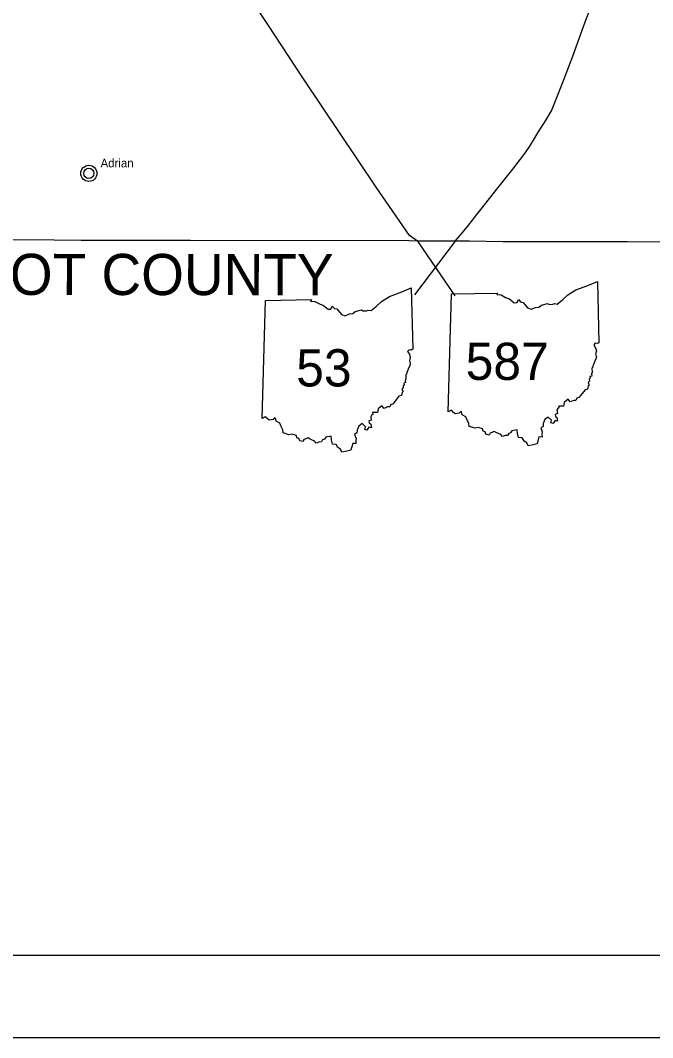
# Model space of a CAD drawing. Extents: x 0 to 882, y 0 to 440.
# Drawn here: x 198.3 to 275.2, y 0 to 123.7 of the extents above; entities that cross this region are included whole.
import ezdxf

# ---------------------------------------------------------------- set-up
doc = ezdxf.new("R2010")
doc.units = 0
for name, color, linetype in [('DV_X_Corp_Line', 7, 'Continuous'), ('GM_X_Adjacent_County_Text', 7, 'Continuous'), ('GM_X_County', 7, 'Continuous'), ('GM_X_State_Route', 7, 'Continuous'), ('PV_P_Text', 7, 'Continuous'), ('SH_Border', 7, 'Continuous'), ('SH_Cut_Line', 7, 'Continuous')]:
    doc.layers.add(name, color=color, linetype=linetype)

msp = doc.modelspace()

# ---------------------------------------------------------------- linework, layer by layer
at = {"layer": 'DV_X_Corp_Line'}
for radius in [0.982, 0.623]:
    msp.add_circle((206.66, 105.09), radius, dxfattribs=at)
at = {"layer": 'GM_X_County'}
msp.add_lwpolyline([(288.04, 96.73), (272.14, 96.76), (257.02, 96.78), (252.97, 96.84), (251.84, 96.84), (251.2, 96.83), (250.6, 96.83), (248.98, 96.85), (246.64, 96.86), (245.6, 96.87), (219.03, 96.94), (205.74, 96.92), (202.42, 96.96), (179.18, 97.04)], dxfattribs=at)
at = {"layer": 'GM_X_State_Route'}
for p, q in [((251.2, 96.83), (246.28, 90.34)), ((246.64, 96.86), (251.16, 90.19))]:
    msp.add_line(p, q, dxfattribs=at)
for points in [[(246.64, 96.86), (245.65, 97.52), (241.61, 103.4), (237.16, 110.07), (232.76, 116.59), (228.43, 123.2), (225.14, 128.19), (224.68, 128.87), (224.33, 129.39), (223.95, 129.96), (219.55, 136.71), (219.48, 136.82), (215.2, 143.29), (212.66, 147.14)], [(254.33, 100.7), (256.44, 103.39), (258.23, 105.6), (259.68, 107.49), (260.38, 108.5), (260.76, 109.14), (261.29, 110), (262.29, 111.6), (262.93, 112.69), (263.52, 114.12), (264.28, 116.06), (265.51, 119.32), (266.87, 123.06), (269.35, 129.63)], [(251.2, 96.83), (252.2, 97.98), (252.87, 98.83), (253.31, 99.4), (253.57, 99.73), (253.84, 100.08), (254.33, 100.7)]]:
    msp.add_lwpolyline(points, dxfattribs=at)
at = {"layer": 'PV_P_Text'}
for p, q in [((250.38, 76.08), (250.78, 90.44)), ((250.38, 76.08), (250.78, 90.44)), ((227.74, 75.28), (228.14, 89.65)), ((227.74, 75.28), (228.14, 89.65))]:
    msp.add_line(p, q, dxfattribs=at)
for points in [[(250.78, 90.44), (256.36, 90.53), (256.27, 90.36), (256.8, 90.32), (257.35, 90.01), (257.83, 89.82), (258.4, 89.36), (258.75, 89.37), (258.9, 89.74), (259.16, 89.45), (259.48, 89.4), (260.02, 88.72), (260.47, 88.57), (261, 88.8), (261.41, 88.84), (261.7, 89.07), (262.46, 89.27), (262.68, 89.15), (263.08, 89.18), (263.29, 89.27), (263.64, 89.19), (264.26, 89.71), (264.9, 90.33), (265.88, 90.91), (267.35, 91.46), (268.52, 91.95), (268.69, 84.5)], [(250.78, 90.44), (256.36, 90.53), (256.27, 90.36), (256.8, 90.32), (257.35, 90.01), (257.83, 89.82), (258.4, 89.36), (258.75, 89.37), (258.9, 89.74), (259.16, 89.45), (259.48, 89.4), (260.02, 88.72), (260.47, 88.57), (261, 88.8), (261.41, 88.84), (261.7, 89.07), (262.46, 89.27), (262.68, 89.15), (263.08, 89.18), (263.29, 89.27), (263.64, 89.19), (264.26, 89.71), (264.9, 90.33), (265.88, 90.91), (267.35, 91.46), (268.52, 91.95), (268.69, 84.5)], [(228.14, 89.65), (233.72, 89.74), (233.63, 89.57), (234.16, 89.53), (234.71, 89.22), (235.19, 89.03), (235.76, 88.57), (236.11, 88.58), (236.26, 88.95), (236.52, 88.66), (236.84, 88.61), (237.38, 87.92), (237.83, 87.78), (238.36, 88.01), (238.77, 88.05), (239.06, 88.28), (239.82, 88.48), (240.04, 88.36), (240.44, 88.39), (240.65, 88.47), (241, 88.4), (241.62, 88.92), (242.26, 89.53), (243.24, 90.11), (244.71, 90.67), (245.88, 91.16), (246.05, 83.7)], [(228.14, 89.65), (233.72, 89.74), (233.63, 89.57), (234.16, 89.53), (234.71, 89.22), (235.19, 89.03), (235.76, 88.57), (236.11, 88.58), (236.26, 88.95), (236.52, 88.66), (236.84, 88.61), (237.38, 87.92), (237.83, 87.78), (238.36, 88.01), (238.77, 88.05), (239.06, 88.28), (239.82, 88.48), (240.04, 88.36), (240.44, 88.39), (240.65, 88.47), (241, 88.4), (241.62, 88.92), (242.26, 89.53), (243.24, 90.11), (244.71, 90.67), (245.88, 91.16), (246.05, 83.7)], [(268.69, 84.5), (268.51, 84.39), (268.25, 84.44), (268.07, 84.23), (268.29, 83.88), (268.39, 83.51), (268.3, 83.11), (268.39, 82.77), (268.33, 82.49), (268.16, 82.21), (268.1, 81.95), (267.96, 81.67), (267.97, 81.51), (267.84, 81.39), (267.86, 80.92), (267.79, 80.66), (267.82, 80.44), (267.6, 80.38), (267.65, 80.2), (267.51, 80.05), (267.54, 79.81), (267.38, 79.65), (267.53, 79.34), (267.41, 79.24), (267.31, 78.86), (267.02, 78.78), (266.46, 78.09), (266.26, 77.83), (266.03, 77.76), (265.91, 77.49), (265.63, 77.49), (265.21, 77.3), (264.94, 77.62), (264.47, 77.24), (264.41, 76.79), (263.81, 76.8), (263.84, 76.58), (263.7, 76.51), (263.58, 76.28), (263.65, 75.88), (263.37, 75.78), (263.4, 75.54), (263.58, 75.4), (263.66, 74.95), (263.37, 75.04), (263.12, 74.67), (262.87, 74.76), (262.95, 75.07), (262.53, 75.46), (262.13, 75.15), (261.92, 74.66), (261.91, 74.33), (261.62, 74.13), (261.81, 73.66), (261.77, 73.34), (261.78, 73.03), (261.4, 73.05), (261.18, 72.22)], [(268.69, 84.5), (268.51, 84.39), (268.25, 84.44), (268.07, 84.23), (268.29, 83.88), (268.39, 83.51), (268.3, 83.11), (268.39, 82.77), (268.33, 82.49), (268.16, 82.21), (268.1, 81.95), (267.96, 81.67), (267.97, 81.51), (267.84, 81.39), (267.86, 80.92), (267.79, 80.66), (267.82, 80.44), (267.6, 80.38), (267.65, 80.2), (267.51, 80.05), (267.54, 79.81), (267.38, 79.65), (267.53, 79.34), (267.41, 79.24), (267.31, 78.86), (267.02, 78.78), (266.46, 78.09), (266.26, 77.83), (266.03, 77.76), (265.91, 77.49), (265.63, 77.49), (265.21, 77.3), (264.94, 77.62), (264.47, 77.24), (264.41, 76.79), (263.81, 76.8), (263.84, 76.58), (263.7, 76.51), (263.58, 76.28), (263.65, 75.88), (263.37, 75.78), (263.4, 75.54), (263.58, 75.4), (263.66, 74.95), (263.37, 75.04), (263.12, 74.67), (262.87, 74.76), (262.95, 75.07), (262.53, 75.46), (262.13, 75.15), (261.92, 74.66), (261.91, 74.33), (261.62, 74.13), (261.81, 73.66), (261.77, 73.34), (261.78, 73.03), (261.4, 73.05), (261.18, 72.22)], [(246.05, 83.7), (245.87, 83.6), (245.61, 83.65), (245.43, 83.44), (245.65, 83.09), (245.75, 82.72), (245.66, 82.32), (245.75, 81.98), (245.69, 81.7), (245.52, 81.42), (245.46, 81.16), (245.32, 80.88), (245.33, 80.72), (245.2, 80.59), (245.22, 80.13), (245.15, 79.87), (245.18, 79.65), (244.96, 79.59), (245.01, 79.4), (244.87, 79.26), (244.9, 79.02), (244.74, 78.86), (244.89, 78.55), (244.77, 78.45), (244.67, 78.07), (244.38, 77.99), (243.82, 77.3), (243.62, 77.03), (243.39, 76.97), (243.27, 76.7), (242.99, 76.7), (242.57, 76.51), (242.3, 76.83), (241.83, 76.44), (241.77, 76), (241.17, 76.01), (241.2, 75.78), (241.06, 75.72), (240.94, 75.49), (241.01, 75.09), (240.73, 74.99), (240.76, 74.75), (240.94, 74.61), (241.02, 74.16), (240.73, 74.25), (240.48, 73.88), (240.23, 73.96), (240.31, 74.28), (239.89, 74.67), (239.49, 74.36), (239.28, 73.87), (239.27, 73.54), (238.98, 73.34), (239.17, 72.87), (239.13, 72.55), (239.14, 72.24), (238.76, 72.25), (238.54, 71.43)], [(246.05, 83.7), (245.87, 83.6), (245.61, 83.65), (245.43, 83.44), (245.65, 83.09), (245.75, 82.72), (245.66, 82.32), (245.75, 81.98), (245.69, 81.7), (245.52, 81.42), (245.46, 81.16), (245.32, 80.88), (245.33, 80.72), (245.2, 80.59), (245.22, 80.13), (245.15, 79.87), (245.18, 79.65), (244.96, 79.59), (245.01, 79.4), (244.87, 79.26), (244.9, 79.02), (244.74, 78.86), (244.89, 78.55), (244.77, 78.45), (244.67, 78.07), (244.38, 77.99), (243.82, 77.3), (243.62, 77.03), (243.39, 76.97), (243.27, 76.7), (242.99, 76.7), (242.57, 76.51), (242.3, 76.83), (241.83, 76.44), (241.77, 76), (241.17, 76.01), (241.2, 75.78), (241.06, 75.72), (240.94, 75.49), (241.01, 75.09), (240.73, 74.99), (240.76, 74.75), (240.94, 74.61), (241.02, 74.16), (240.73, 74.25), (240.48, 73.88), (240.23, 73.96), (240.31, 74.28), (239.89, 74.67), (239.49, 74.36), (239.28, 73.87), (239.27, 73.54), (238.98, 73.34), (239.17, 72.87), (239.13, 72.55), (239.14, 72.24), (238.76, 72.25), (238.54, 71.43)], [(238.54, 71.43), (237.89, 71.27), (237.44, 71.18), (237.28, 71.55), (236.95, 71.75), (236.74, 72.13), (236.28, 72.18), (236.17, 72.7), (236.12, 73.12), (235.48, 73.01), (235.31, 72.76), (235.09, 72.69), (234.96, 72.43), (234.65, 72.41), (234.32, 72.28), (234.1, 72.54), (233.57, 72.79), (233.32, 72.92), (232.82, 72.72), (232.71, 72.48), (232.31, 72.58), (232.21, 72.85), (231.97, 72.94), (231.91, 73.22), (231.39, 73.37), (230.99, 73.31), (230.29, 73.54), (230.25, 73.92), (230.01, 74.38), (229.88, 74.7), (229.44, 74.94), (229.35, 75.32), (229.21, 75.31), (229.08, 75.15), (228.58, 75.08), (228.38, 75.24), (228.11, 75.5), (227.74, 75.28)], [(238.54, 71.43), (237.89, 71.27), (237.44, 71.18), (237.28, 71.55), (236.95, 71.75), (236.74, 72.13), (236.28, 72.18), (236.17, 72.7), (236.12, 73.12), (235.48, 73.01), (235.31, 72.76), (235.09, 72.69), (234.96, 72.43), (234.65, 72.41), (234.32, 72.28), (234.1, 72.54), (233.57, 72.79), (233.32, 72.92), (232.82, 72.72), (232.71, 72.48), (232.31, 72.58), (232.21, 72.85), (231.97, 72.94), (231.91, 73.22), (231.39, 73.37), (230.99, 73.31), (230.29, 73.54), (230.25, 73.92), (230.01, 74.38), (229.88, 74.7), (229.44, 74.94), (229.35, 75.32), (229.21, 75.31), (229.08, 75.15), (228.58, 75.08), (228.38, 75.24), (228.11, 75.5), (227.74, 75.28)], [(261.18, 72.22), (260.53, 72.06), (260.08, 71.97), (259.92, 72.34), (259.59, 72.54), (259.38, 72.92), (258.92, 72.97), (258.81, 73.49), (258.76, 73.91), (258.12, 73.8), (257.95, 73.55), (257.73, 73.48), (257.6, 73.22), (257.29, 73.2), (256.96, 73.08), (256.75, 73.33), (256.21, 73.58), (255.96, 73.72), (255.46, 73.51), (255.35, 73.27), (254.95, 73.38), (254.85, 73.65), (254.61, 73.73), (254.55, 74.01), (254.03, 74.17), (253.63, 74.1), (252.93, 74.33), (252.89, 74.71), (252.65, 75.17), (252.52, 75.49), (252.08, 75.73), (251.99, 76.11), (251.85, 76.1), (251.72, 75.95), (251.22, 75.87), (251.02, 76.03), (250.75, 76.29), (250.38, 76.08)], [(261.18, 72.22), (260.53, 72.06), (260.08, 71.97), (259.92, 72.34), (259.59, 72.54), (259.38, 72.92), (258.92, 72.97), (258.81, 73.49), (258.76, 73.91), (258.12, 73.8), (257.95, 73.55), (257.73, 73.48), (257.6, 73.22), (257.29, 73.2), (256.96, 73.08), (256.75, 73.33), (256.21, 73.58), (255.96, 73.72), (255.46, 73.51), (255.35, 73.27), (254.95, 73.38), (254.85, 73.65), (254.61, 73.73), (254.55, 74.01), (254.03, 74.17), (253.63, 74.1), (252.93, 74.33), (252.89, 74.71), (252.65, 75.17), (252.52, 75.49), (252.08, 75.73), (251.99, 76.11), (251.85, 76.1), (251.72, 75.95), (251.22, 75.87), (251.02, 76.03), (250.75, 76.29), (250.38, 76.08)]]:
    msp.add_lwpolyline(points, dxfattribs=at)
at = {"layer": 'SH_Border'}
msp.add_lwpolyline([(30, 430), (670, 430), (670, 10), (30, 10)], close=True, dxfattribs=at)
at = {"layer": 'SH_Cut_Line'}
msp.add_lwpolyline([(0, 0), (680, 0), (680, 440), (0, 440)], close=True, dxfattribs=at)

# ---------------------------------------------------------------- texts
at = {"layer": 'DV_X_Corp_Line'}
msp.add_text('Adrian', height=1.042, rotation=0, dxfattribs=at).set_placement((208.08, 105.82))
at = {"layer": 'GM_X_Adjacent_County_Text'}
msp.add_text('WYANDOT COUNTY', height=5, rotation=359.9356, dxfattribs=at).set_placement((172.16, 90.34))
at = {"layer": 'PV_P_Text'}
for s, p in [('587', (252.49, 79.97)), ('53', (231.88, 79.18))]:
    msp.add_text(s, height=4.528, dxfattribs=at).set_placement(p)

doc.saveas('drawing.dxf')
